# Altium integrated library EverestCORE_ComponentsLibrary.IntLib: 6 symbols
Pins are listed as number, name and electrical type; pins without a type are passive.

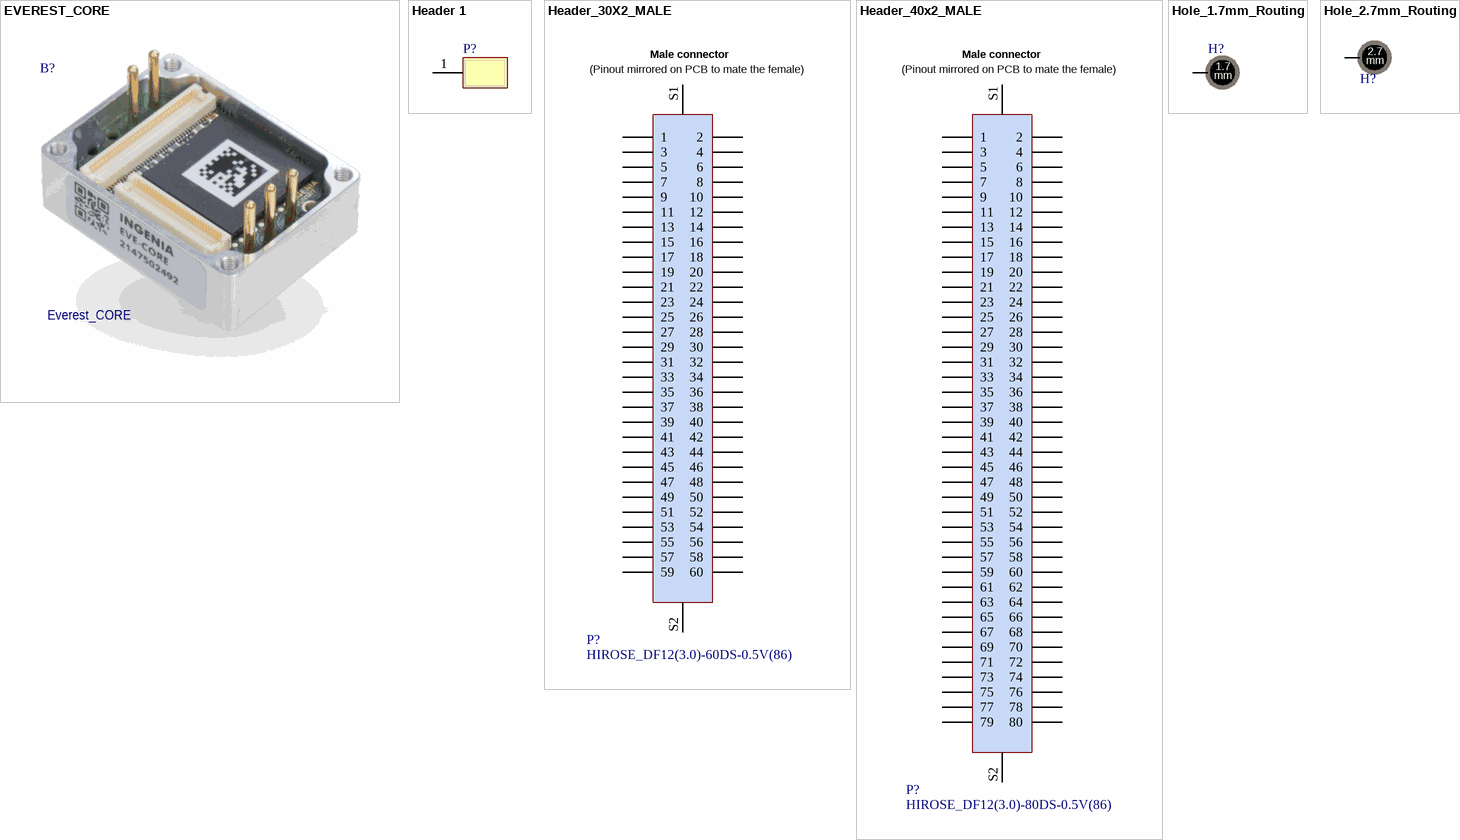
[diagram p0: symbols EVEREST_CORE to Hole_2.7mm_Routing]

## EVEREST_CORE
designator B?, comment Everest_CORE
Everest CORE high-performance Servo Drive from Ingenia Motion Control.; ManufacturerPN: EVE-CORE; IsPreferred: 0; IngeniaID: 4681; TemperatureMaxC: 85; TemperatureMinC: -40
footprint EVEREST_CORE

## Header 1
designator P?
1pin, receptacle for MillMax 6142, pass-through; ManufacturerPN: 9372-0-15-15-23-27-10-0; CompletePN: MillMax_9372-0-15-15-23-27-10-0; IsPreferred: 0; IngeniaID: 3714; TemperatureMaxC: 125; TemperatureMinC: -55
footprint MillMax_9372-0-15-15-23-27-10-0_HD
pins: 1

## Header_30X2_MALE
designator P?, comment HIROSE_DF12(3.0)-60DS-0.5V(86)
Connector SMD Mezzanine, 60 ways, 0.5mm pitch, 3mm stack height. Male; ManufacturerName: Hirose; IsPreferred: 0; IngeniaID: 3207; TemperatureMaxC: 125; TemperatureMinC: -45
footprint HIROSE_DF12(3.0)-60DS-0.5V(86)
pins: 1, 2, 3, 4, 5, 6, 7, 8, 9, 10, 11, 12, 13, 14, 15, 16, 17, 18, 19, 20, 21, 22, 23, 24, 25, 26, 27, 28, 29, 30, 31, 32, 33, 34, 35, 36, 37, 38, 39, 40, 41, 42, 43, 44, 45, 46, 47, 48, 49, 50, 51, 52, 53, 54, 55, 56, 57, 58, 59, 60, S1 shield1, S2 Shield2

## Header_40x2_MALE
designator P?, comment HIROSE_DF12(3.0)-80DS-0.5V(86)
Connector SMD Mezzanine, 80 ways, 0.5mm pitch, 3mm stack height. Male with metal fitting and boss; ManufacturerName: Hirose; IsPreferred: 1; IsGeneric: 0; IngeniaID: 3721; TemperatureMaxC: 125; TemperatureMinC: -45; MTBF55h: 176336644
footprint HIROSE_DF12(3.0)-80DS-0.5V(86)
pins: 1, 2, 3, 4, 5, 6, 7, 8, 9, 10, 11, 12, 13, 14, 15, 16, 17, 18, 19, 20, 21, 22, 23, 24, 25, 26, 27, 28, 29, 30, 31, 32, 33, 34, 35, 36, 37, 38, 39, 40, 41, 42, 43, 44, 45, 46, 47, 48, 49, 50, 51, 52, 53, 54, 55, 56, 57, 58, 59, 60, 61, 62, 63, 64, 65, 66, 67, 68, 69, 70, 71, 72, 73, 74, 75, 76, 77, 78, 79, 80, S1 Shield2, S2 Shield2

## Hole_1.7mm_Routing
designator H?  (no BOM)
Mounting, plated hole, 1.7 mm diameter; ManufacturerName: Ingenia; CompletePN: Hole_1.7mm_Routing; IsPreferred: 0; IngeniaID: 4513
footprint Hole_1.7mm_Routing
pins: 1

## Hole_2.7mm_Routing
designator H?  (no BOM)
Mounting, plated hole, 2.7 mm diameter; ManufacturerName: Ingenia; CompletePN: Hole_2.7mm_Routing; IsPreferred: 1; IsGeneric: 0; IngeniaID: 3160
footprint Hole_2.7mm_Routing
pins: 1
